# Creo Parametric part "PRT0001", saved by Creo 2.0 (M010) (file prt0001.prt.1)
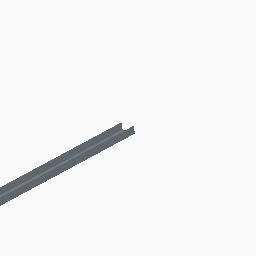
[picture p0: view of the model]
Units: Inch lbm Second (Pro/E Default); INCH, POUND, SECS

Created from: INLBS_PART_SOLID.PRT

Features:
  1. datum plane "RIGHT"
  2. datum plane "TOP"
  3. datum plane "FRONT"
  4. coordinate system
  5. sketch "Sketch 1"
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
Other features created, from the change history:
  extrusion "Extrude 1"

Surfaces: 13 plane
